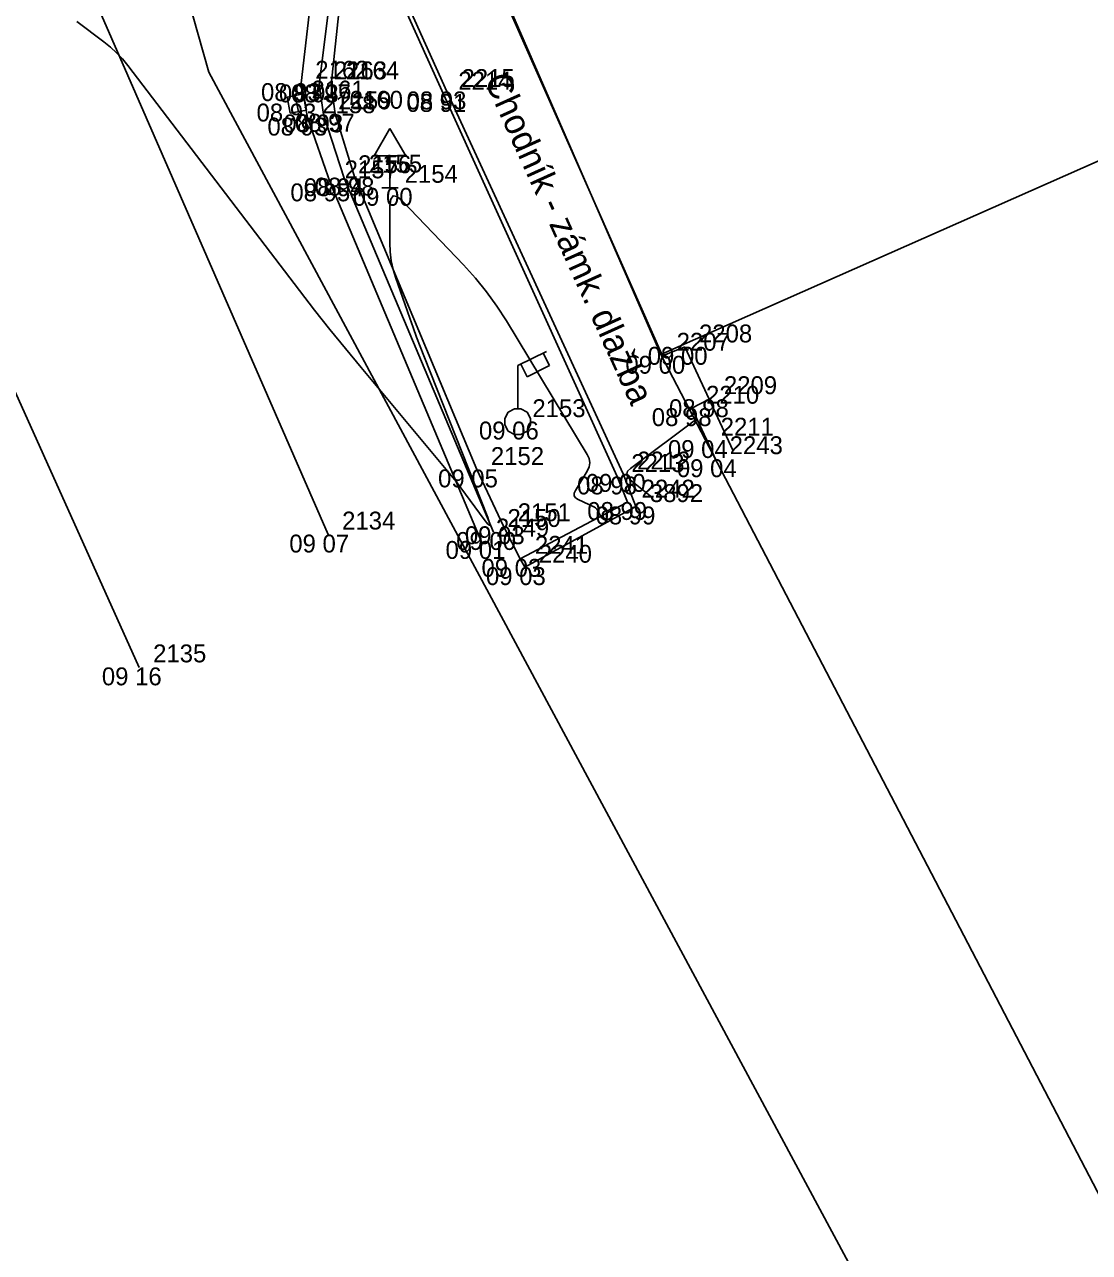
# Model space of a CAD drawing. Extents: x -703403 to -701924, y -1022520 to -1021856.
# Drawn here: x -702850.09 to -702833.42, y -1021972.4 to -1021953.17 of the extents above; entities that cross this region are included whole.
import ezdxf

# ---------------------------------------------------------------- set-up
doc = ezdxf.new("R2010")
doc.units = 0
for name, color, linetype in [('Ex_Major Contours', 7, 'Continuous'), ('Z_body', 7, 'Continuous'), ('Z_body_cisla', 7, 'Continuous'), ('Z_body_vysky_redukovane', 7, 'Continuous'), ('Z_budova', 7, 'Continuous'), ('Z_chodnik', 7, 'Continuous'), ('Z_dopravni_znacky', 7, 'Continuous'), ('Z_katastr_hranice', 7, 'Continuous'), ('Z_katastr_vnitrni_kresba', 7, 'Continuous'), ('Z_komunikace', 7, 'Continuous'), ('Z_obruba', 7, 'Continuous'), ('Z_ploty', 7, 'Continuous'), ('Z_popisy', 7, 'Continuous'), ('Z_rozhranni', 7, 'Continuous'), ('Z_site_kanalizace_znaky', 7, 'Continuous'), ('Z_site_vo_znaky', 7, 'Continuous'), ('Z_vdz13_prerusovana', 7, 'Continuous'), ('Z_VDZ_25_prerus', 7, 'Continuous'), ('Z_vstupy', 7, 'Continuous')]:
    doc.layers.add(name, color=color, linetype=linetype)

# ---------------------------------------------------------------- blocks, each defined once
blk = doc.blocks.new('POINT_DISPLAY')
blk.add_line((0, 0), (0, 0))
blk = doc.blocks.new('Z13')
for p, q in [((0, 0.88), (0.45, 1.1)), ((0.4, 1.07), (0.5, 0.88)), ((0, 0.2), (0, 0.88)), ((0.15, 0.7), (0.05, 0.9)), ((0.5, 0.88), (0.15, 0.7)), ((-0.15, 0.15), (-0.05, 0.2)), ((-0.05, 0.2), (0.05, 0.2)), ((0.05, 0.2), (0.15, 0.15)), ((-0.2, 0.05), (-0.15, 0.15)), ((-0.2, -0.05), (-0.2, 0.05)), ((0.15, 0.15), (0.2, 0.05)), ((0.2, 0.05), (0.2, -0.05)), ((-0.15, -0.15), (-0.2, -0.05)), ((-0.05, -0.2), (-0.15, -0.15)), ((0.15, -0.15), (0.05, -0.2)), ((0.2, -0.05), (0.15, -0.15)), ((0.05, -0.2), (-0.05, -0.2))]:
    blk.add_line(p, q)
blk = doc.blocks.new('Z46260')
for p, q in [((0.13, 0.13), (-0.13, 0.13)), ((-0.13, 0.13), (-0.13, -0.13)), ((0.13, 0), (-0.13, 0)), ((0.13, -0.13), (0.13, 0.13)), ((-0.13, -0.13), (0.13, -0.13))]:
    blk.add_line(p, q)
blk = doc.blocks.new('Z527')
for p, q in [((0, 0.93), (-0.25, 0.5)), ((0.25, 0.5), (0, 0.93)), ((-0.25, 0.5), (0.25, 0.5)), ((0, 0), (0, 0.5)), ((-0.13, 0), (0.13, 0))]:
    blk.add_line(p, q)

msp = doc.modelspace()

# ---------------------------------------------------------------- linework, layer by layer
at = {"layer": 'Ex_Major Contours'}
for points in [[(-702840.955, -1021960.958), (-702841.044, -1021960.909), (-702841.048, -1021960.907), (-702841.052, -1021960.904), (-702841.054, -1021960.901), (-702841.057, -1021960.897), (-702841.07, -1021960.872), (-702841.074, -1021960.864), (-702841.119, -1021960.777), (-702841.128, -1021960.762), (-702841.139, -1021960.749), (-702841.152, -1021960.738), (-702841.167, -1021960.73), (-702841.425, -1021960.608), (-702841.464, -1021960.582), (-702841.484, -1021960.551), (-702841.485, -1021960.513), (-702841.466, -1021960.471), (-702841.281, -1021960.167), (-702841.25, -1021960.101), (-702841.24, -1021960.035), (-702841.25, -1021959.969), (-702841.28, -1021959.903), (-702842.546, -1021957.813), (-702842.696, -1021957.58), (-702842.858, -1021957.356), (-702843.032, -1021957.142), (-702843.218, -1021956.936), (-702844.172, -1021955.937), (-702844.259, -1021955.864), (-702844.321, -1021955.853), (-702844.358, -1021955.904), (-702844.371, -1021956.016), (-702844.373, -1021956.589), (-702844.368, -1021956.731), (-702844.35, -1021956.872), (-702844.321, -1021957.01), (-702844.279, -1021957.146), (-702844.06, -1021957.769), (-702844.007, -1021957.918), (-702843.953, -1021958.066), (-702843.897, -1021958.214), (-702843.839, -1021958.361), (-702842.84, -1021960.891), (-702842.81, -1021960.979), (-702842.809, -1021961.013), (-702842.838, -1021960.994), (-702842.896, -1021960.922), (-702843.188, -1021960.525), (-702843.261, -1021960.426), (-702843.336, -1021960.329), (-702843.413, -1021960.233), (-702843.491, -1021960.138), (-702844.821, -1021958.545), (-702845.067, -1021958.247), (-702845.31, -1021957.946), (-702845.55, -1021957.643), (-702845.786, -1021957.337), (-702848.478, -1021953.811), (-702848.562, -1021953.709), (-702848.651, -1021953.613), (-702848.748, -1021953.524), (-702848.85, -1021953.441), (-702849.274, -1021953.122)], [(-702839.75, -1021958.22), (-702840.013, -1021958.325), (-702840.053, -1021958.346), (-702840.086, -1021958.374), (-702840.111, -1021958.408), (-702840.13, -1021958.449), (-702840.1, -1021958.36)], [(-702840.27, -1021960.572), (-702840.608, -1021960.301), (-702840.649, -1021960.256), (-702840.663, -1021960.211), (-702840.648, -1021960.167), (-702840.604, -1021960.124), (-702839.563, -1021959.347)]]:
    msp.add_lwpolyline(points, dxfattribs=at)
at = {"layer": 'Z_budova'}
for p, q in [((-702842.89, -1021952.06), (-702840.1, -1021958.36)), ((-702840.1, -1021958.36), (-702839.75, -1021958.22))]:
    msp.add_line(p, q, dxfattribs=at)
at = {"layer": 'Z_chodnik'}
for p, q in [((-702843.48, -1021954.22), (-702844.82, -1021951.25)), ((-702840.72, -1021960.21), (-702843.48, -1021954.22)), ((-702840.52, -1021960.72), (-702840.72, -1021960.21)), ((-702842.26, -1021961.67), (-702840.52, -1021960.72))]:
    msp.add_line(p, q, dxfattribs=at)
at = {"layer": 'Z_katastr_hranice'}
for p, q in [((-702872.979, -1021862.006), (-702847.21, -1021953.92)), ((-702842.88, -1021952.02), (-702840.13, -1021958.34)), ((-702847.21, -1021953.92), (-702823.381, -1021998.246)), ((-702840.13, -1021958.34), (-702832.86, -1021972.28))]:
    msp.add_line(p, q, dxfattribs=at)
at = {"layer": 'Z_katastr_vnitrni_kresba'}
msp.add_line((-702840.13, -1021958.34), (-702808.44, -1021944.33), dxfattribs=at)
at = {"layer": 'Z_komunikace'}
for p, q in [((-702845.48, -1021954.11), (-702845.29, -1021952.6)), ((-702845.41, -1021954.58), (-702845.48, -1021954.11)), ((-702845.09, -1021955.58), (-702845.41, -1021954.58)), ((-702842.75, -1021961.12), (-702845.09, -1021955.58))]:
    msp.add_line(p, q, dxfattribs=at)
at = {"layer": 'Z_obruba'}
for p, q in [((-702843.53, -1021954.26), (-702844.84, -1021951.38)), ((-702845.29, -1021954.11), (-702845.13, -1021952.6)), ((-702845.23, -1021954.57), (-702845.29, -1021954.11)), ((-702840.81, -1021960.25), (-702843.53, -1021954.26)), ((-702844.92, -1021955.57), (-702845.23, -1021954.57)), ((-702843.01, -1021960.14), (-702844.92, -1021955.57)), ((-702842.59, -1021961.03), (-702843.01, -1021960.14)), ((-702840.81, -1021960.25), (-702840.65, -1021960.65)), ((-702842.33, -1021961.54), (-702840.65, -1021960.65)), ((-702842.59, -1021961.03), (-702842.33, -1021961.54)), ((-702842.26, -1021961.67), (-702842.33, -1021961.54))]:
    msp.add_line(p, q, dxfattribs=at)
at = {"layer": 'Z_ploty'}
for p, q in [((-702839.37, -1021959.04), (-702839.64, -1021959.18)), ((-702839.37, -1021959.04), (-702839, -1021959.84)), ((-702839.64, -1021959.18), (-702839.41, -1021959.68)), ((-702839.41, -1021959.68), (-702839.27, -1021959.98))]:
    msp.add_line(p, q, dxfattribs=at)
at = {"layer": 'Z_rozhranni'}
for p, q in [((-702845.76, -1021954.09), (-702845.58, -1021952.54)), ((-702845.66, -1021954.63), (-702845.76, -1021954.09)), ((-702845.3, -1021955.66), (-702845.66, -1021954.63)), ((-702842.94, -1021961.26), (-702845.3, -1021955.66))]:
    msp.add_line(p, q, dxfattribs=at)
at = {"layer": 'Z_vdz13_prerusovana'}
msp.add_line((-702848.3, -1021963.24), (-702851.74, -1021955.62), dxfattribs=at)
at = {"layer": 'Z_VDZ_25_prerus'}
msp.add_line((-702849.11, -1021952.52), (-702845.34, -1021961.16), dxfattribs=at)
at = {"layer": 'Z_vstupy'}
msp.add_line((-702839.75, -1021958.22), (-702839.37, -1021959.04), dxfattribs=at)

# ---------------------------------------------------------------- block references
at = {"layer": 'Z_body'}
for p in [(-702845.76, -1021954.09), (-702845.48, -1021954.11), (-702845.29, -1021954.11), (-702843.53, -1021954.26), (-702843.48, -1021954.22), (-702845.83, -1021954.41), (-702845.66, -1021954.63), (-702845.41, -1021954.58), (-702845.23, -1021954.57), (-702845.09, -1021955.58), (-702844.92, -1021955.57), (-702845.3, -1021955.66), (-702844.37, -1021955.73), (-702839.75, -1021958.22), (-702840.1, -1021958.36), (-702839.37, -1021959.04), (-702839.64, -1021959.18), (-702842.37, -1021959.39), (-702839.41, -1021959.68), (-702839.27, -1021959.98), (-702843.01, -1021960.14), (-702840.81, -1021960.25), (-702840.72, -1021960.21), (-702840.65, -1021960.65), (-702840.52, -1021960.72), (-702842.59, -1021961.03), (-702845.34, -1021961.16), (-702842.75, -1021961.12), (-702842.94, -1021961.26), (-702842.33, -1021961.54), (-702842.26, -1021961.67), (-702848.3, -1021963.24)]:
    msp.add_blockref('POINT_DISPLAY', p, dxfattribs=at)
at = {"layer": 'Z_dopravni_znacky'}
msp.add_blockref('Z527', (-702844.37, -1021955.73), dxfattribs=at)
at = {"layer": 'Z_site_kanalizace_znaky', "rotation": -79.20000000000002}
msp.add_blockref('Z46260', (-702845.83, -1021954.41), dxfattribs=at)
at = {"layer": 'Z_site_vo_znaky'}
msp.add_blockref('Z13', (-702842.37, -1021959.39), dxfattribs=at)

# ---------------------------------------------------------------- texts
at = {"layer": 'Z_body_cisla'}
for s, p in [('2162', (-702845.54, -1021954.02)), ('2163', (-702845.25, -1021954.03)), ('2164', (-702845.06, -1021954.03)), ('2214', (-702843.3, -1021954.19)), ('2215', (-702843.25, -1021954.15)), ('2161', (-702845.6, -1021954.33)), ('2158', (-702845.43, -1021954.56)), ('2159', (-702845.18, -1021954.5)), ('2160', (-702845, -1021954.49)), ('2156', (-702844.87, -1021955.5)), ('2155', (-702844.7, -1021955.49)), ('2157', (-702845.08, -1021955.58)), ('2154', (-702844.14, -1021955.65)), ('2208', (-702839.53, -1021958.15)), ('2207', (-702839.88, -1021958.28)), ('2209', (-702839.14, -1021958.96)), ('2210', (-702839.42, -1021959.11)), ('2153', (-702842.14, -1021959.32)), ('2211', (-702839.19, -1021959.61)), ('2243', (-702839.05, -1021959.9)), ('2152', (-702842.79, -1021960.07)), ('2212', (-702840.5, -1021960.14)), ('2213', (-702840.59, -1021960.18)), ('2242', (-702840.43, -1021960.58)), ('3892', (-702840.3, -1021960.65)), ('2134', (-702845.12, -1021961.08)), ('2150', (-702842.53, -1021961.04)), ('2151', (-702842.37, -1021960.95)), ('2149', (-702842.71, -1021961.19)), ('2241', (-702842.1, -1021961.46)), ('2240', (-702842.04, -1021961.6)), ('2135', (-702848.08, -1021963.16))]:
    msp.add_text(s, height=0.28, dxfattribs=at).set_placement(p)
at = {"layer": 'Z_body_vysky_redukovane'}
for s, p in [('08 93', (-702846.39, -1021954.37)), ('08 93', (-702846.11, -1021954.39)), ('08 97', (-702845.92, -1021954.39)), ('08 91', (-702844.113, -1021954.54)), ('08 93', (-702844.11, -1021954.5)), ('08 93', (-702846.46, -1021954.69)), ('08 93', (-702846.29, -1021954.91)), ('08 93', (-702846.04, -1021954.86)), ('08 97', (-702845.86, -1021954.85)), ('08 95', (-702845.93, -1021955.94)), ('08 94', (-702845.72, -1021955.86)), ('08 98', (-702845.55, -1021955.85)), ('09 00', (-702844.953, -1021956.01)), ('09 00', (-702840.333, -1021958.5)), ('09 00', (-702840.683, -1021958.64)), ('08 98', (-702840, -1021959.32)), ('08 98', (-702840.27, -1021959.46)), ('09 06', (-702842.977, -1021959.67)), ('09 04', (-702840.017, -1021959.96)), ('09 04', (-702839.877, -1021960.26)), ('09 05', (-702843.617, -1021960.42)), ('08 98', (-702841.44, -1021960.53)), ('09 00', (-702841.303, -1021960.49)), ('08 99', (-702841.28, -1021960.93)), ('08 99', (-702841.15, -1021961)), ('09 03', (-702843.197, -1021961.31)), ('09 07', (-702845.947, -1021961.44)), ('09 00', (-702843.333, -1021961.4)), ('09 01', (-702843.5, -1021961.54)), ('09 03', (-702842.937, -1021961.82)), ('09 03', (-702842.867, -1021961.95)), ('09 16', (-702848.883, -1021963.52))]:
    msp.add_text(s, height=0.28, dxfattribs=at).set_placement(p)
at = {"layer": 'Z_popisy'}
msp.add_text('Chodník - zámk. dlažba', height=0.4, rotation=294.3, dxfattribs=at).set_placement((-702842.9, -1021954.04))

doc.saveas('drawing.dxf')
